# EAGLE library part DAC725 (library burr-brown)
Dual 16-Bit DAC
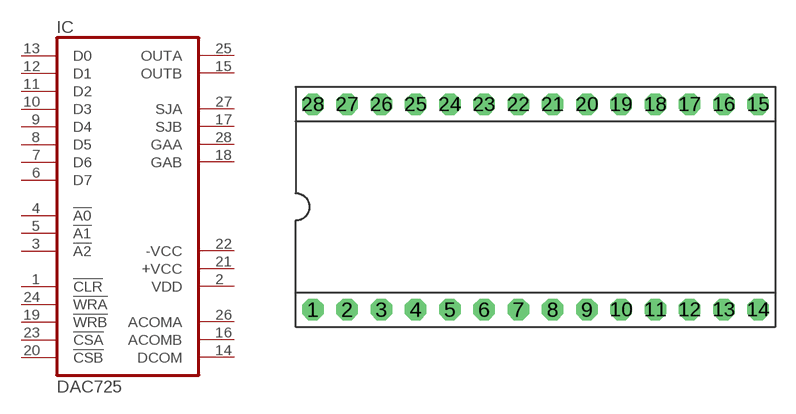
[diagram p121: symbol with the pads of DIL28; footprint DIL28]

Designator prefix IC

## DAC725P (MF: TEXAS INSTRUMENT CONNECTORS; MPN: DAC725JP; OC_FARNELL: unknown; OC_NEWARK: 35C0448)  [DIL28]
1  !CLR  in
2  VDD  pwr
3  !A2  in
4  !A0  in
5  !A1  in
6  D7  in
7  D6  in
8  D5  in
9  D4  in
10  D3  in
11  D2  in
12  D1  in
13  D0  in
14  DCOM  pwr
15  OUTB  out
16  ACOMB  pwr
17  SJB  pas
18  GAB  pas
19  !WRB  in
20  !CSB  in
21  +VCC  pwr
22  -VCC  pwr
23  !CSA  in
24  !WRA  in
25  OUTA  out
26  ACOMA  pwr
27  SJA  pas
28  GAA  pas

## Footprint DIL28 (pad centres in mm)
Dual In Line
drill 0.813 pad 1.6 octagon: 1 -16.51,-7.62; 2 -13.97,-7.62; 3 -11.43,-7.62; 4 -8.89,-7.62; 5 -6.35,-7.62; 6 -3.81,-7.62; 7 -1.27,-7.62; 8 1.27,-7.62; 9 3.81,-7.62; 10 6.35,-7.62; 11 8.89,-7.62; 12 11.43,-7.62; 13 13.97,-7.62; 14 16.51,-7.62; 15 16.51,7.62; 16 13.97,7.62; 17 11.43,7.62; 18 8.89,7.62; 19 6.35,7.62; 20 3.81,7.62; 21 1.27,7.62; 22 -1.27,7.62; 23 -3.81,7.62; 24 -6.35,7.62; 25 -8.89,7.62; 26 -11.43,7.62; 27 -13.97,7.62; 28 -16.51,7.62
